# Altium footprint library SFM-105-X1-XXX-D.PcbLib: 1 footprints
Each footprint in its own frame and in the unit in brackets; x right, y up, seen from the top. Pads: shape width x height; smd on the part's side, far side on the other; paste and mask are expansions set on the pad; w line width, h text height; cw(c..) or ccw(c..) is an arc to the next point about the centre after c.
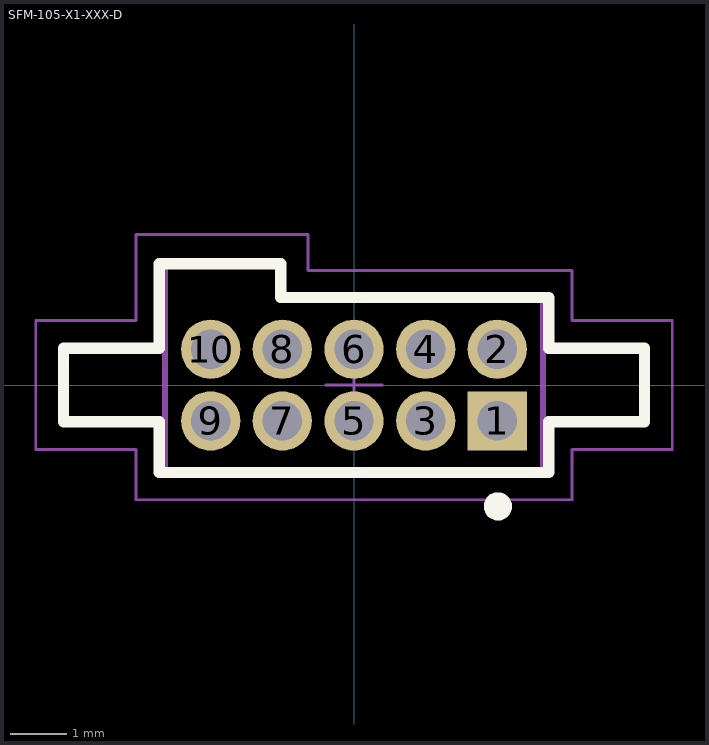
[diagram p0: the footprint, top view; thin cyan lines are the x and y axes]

## SFM-105-X1-XXX-D [mm] "1.27mm pitch, 5 pin, socket strip; double row"
height 4.57
pads (10):
  rect 1.05x1.05 / inner round 1.05 / far side rect 1.05x1.05 hole 0.7 mask+0: 1(2.54,-0.635)
  round 1.05 hole 0.7 mask+0: 2(2.54,0.635) 3(1.27,-0.635) 4(1.27,0.635) 5(0,-0.635) 6(0,0.635) 7(-1.27,-0.635) 8(-1.27,0.635) 9(-2.54,-0.635) 10(-2.54,0.635)
Top Overlay:
  circle w0.25: c2.55,-2.15 r0.125
  lines w0.2: -5.15,-0.65 -5.15,0.65 -3.45,0.65 -3.45,2.15 -1.3,2.15 -1.3,1.55 3.45,1.55 3.45,0.65 5.15,0.65 5.15,-0.65 3.45,-0.65 3.45,-1.55 -3.45,-1.55 -3.45,-0.65 -5.15,-0.65
Mechanical 12:
  lines w0.001: -5.15,-0.65 -5.15,0.65 -3.35,0.65 -3.35,2.15 -1.3,2.15 -1.3,1.55 3.35,1.55 3.35,0.65 5.15,0.65 5.15,-0.65 3.35,-0.65 3.35,-1.55 -3.35,-1.55 -3.35,-0.65 -5.15,-0.65
Mechanical 13:
  lines w0.1: -3.353,-0.65 -5.15,-0.65 -5.15,0.65 -3.353,0.65 ; 3.353,-0.65 5.15,-0.65 5.15,0.65 3.353,0.65 ; -3.35,-1.55 -3.35,2.15 -1.3,2.15 -1.3,1.55 3.35,1.55 3.35,-1.55 -3.35,-1.55
  text ".Designator" at 0,-0.127 h1.52
Mechanical 15:
  lines w0.05: -0.5,0 0.5,0 ; 0,-0.5 0,0.5 ; -5.639,-1.143 -5.639,1.143 -3.861,1.143 -3.861,2.667 -0.813,2.667 -0.813,2.032 3.861,2.032 3.861,1.143 5.639,1.143 5.639,-1.143 3.861,-1.143 3.861,-2.032 -3.861,-2.032 -3.861,-1.143 -5.639,-1.143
